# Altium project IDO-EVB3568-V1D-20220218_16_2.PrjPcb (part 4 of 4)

## Sheet P21.SchDoc
size 297 x 209 mm
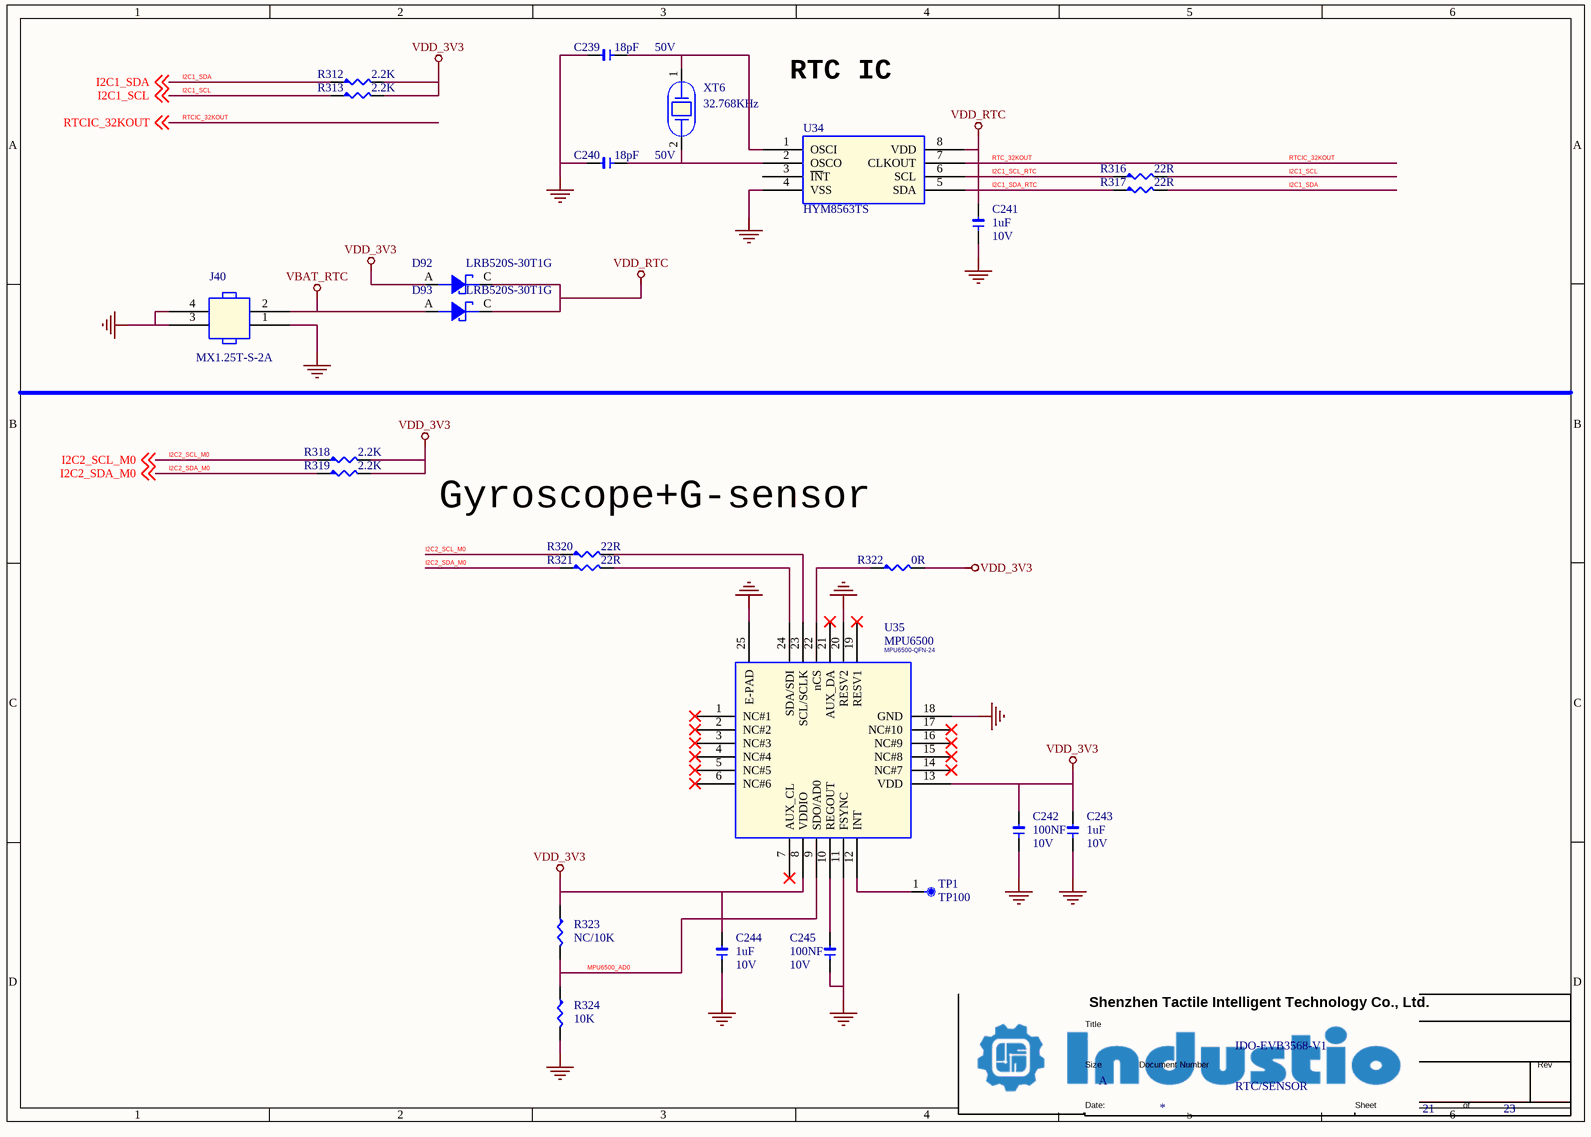
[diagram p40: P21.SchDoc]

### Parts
(Parts that share a designator on the sheet are numbered #1, #2 ... from top to bottom, then left to right.)
*#21  Doc: RTC/SENSOR  Title: IDO-EVB3568-V1  Page Size: A  Page Number: 21  Page Count: 23  (hidden comment: TitleBlock1)  (graphical)
C239  18pF  DSC2: 50V  [1206]
C240  18pF  DSC2: 50V  [1206]
C241  1uF  DSC2: 10V  [1206]
C242  100NF  DSC2: 10V  [1206]
C243  1uF  DSC2: 10V  [1206]
C244  1uF  DSC2: 10V  [1206]
C245  100NF  DSC2: 10V  [1206]
D92  LRB520S-30T1G  [SOD523]
D93  LRB520S-30T1G  [SOD523]
J40  MX1.25T-S-2A  [MX125T-S-2A]
R312  2.2K  [R0402L]
R313  2.2K  [R0402L]
R316  22R  [R0402L]
R317  22R  [R0402L]
R318  2.2K  [R0402L]
R319  2.2K  [R0402L]
R320  22R  [R0402L]
R321  22R  [R0402L]
R322  0R  [R0402L]
R323  NC/10K  [R0402L]
R324  10K  [R0402L]
TP1  TP100  [smd_tp_1mm]
U34  HYM8563TS  [PCF85063ATT-TSSOP8]
U35  MPU6500  [MPU6500-QFN-24]
XT6  32.768KHz  [XTAL_32X15_2P]

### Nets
GND: C239.2 C240.2 C241.1 C242.1 C243.1 C244.1 C245.1 J40.1 J40.3 J40.4 R324.2 U34.4(VSS) U35.11(FSYNC) U35.18(GND) U35.20(RESV2) U35.25(E-PAD)
VBAT_RTC: D93.A J40.2
VDD_3V3: C242.2 C243.2 C244.2 D92.A R312.2 R313.2 R318.2 R319.2 R322.2 R323.1 U35.8(VDDIO) U35.13(VDD)
VDD_RTC: C241.2 D92.C D93.C U34.8(VDD)
I2C1_SCL: R313.1 R316.2 ; off-sheet I2C1_SCL
I2C1_SCL_RTC: R316.1 U34.6(SCL)
I2C1_SDA: R312.1 R317.2 ; off-sheet I2C1_SDA
I2C1_SDA_RTC: R317.1 U34.5(SDA)
I2C2_SCL_M0: R318.1 R320.1 ; off-sheet I2C2_SCL_M0
I2C2_SDA_M0: R319.1 R321.1 ; off-sheet I2C2_SDA_M0
MPU6500_AD0: R323.2 R324.1 U35.9(SDO/AD0)
RTC_32KOUT: U34.7(CLKOUT) ; off-sheet RTCIC_32KOUT  [also labelled RTCIC_32KOUT]
NetC239_1: C239.1 U34.1(OSCI) XT6.1
NetC240_1: C240.1 U34.2(OSCO) XT6.2
NetC245_2: C245.2 U35.10(REGOUT)
NetR320_2: R320.2 U35.23(SCL/SCLK)
NetR321_2: R321.2 U35.24(SDA/SDI)
NetR322_1: R322.1 U35.22(nCS)
NetTP1_1: TP1.1 U35.12(INT)

Not connected (* = marked no-connect by the designer): U34 3(~{IN}T); U35 1(NC#1)* 2(NC#2)* 3(NC#3)* 4(NC#4)* 5(NC#5)* 6(NC#6)* 7(AUX_CL)* 14(NC#7)* 15(NC#8)* 16(NC#9)* 17(NC#10)* 19(RESV1)* 21(AUX_DA)*

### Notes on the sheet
- RTC IC
- Gyroscope+G-sensor

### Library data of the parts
C239 = C-0402_Dup1: Part Number: C020102120027; Part Name: 贴片电容; Manufacture: 三星¦国巨¦村田; ERP Number: 1010200091; DSC1: ±5%; DSC3: C0G; ID: 27; PCB Footprint: C0402L
C240 = C-0402_Dup1: Manufacture: 三星¦国巨¦村田; Part Name: 贴片电容; Part Number: C020102120027; ID: 27; DSC3: C0G; DSC1: ±5%; ERP Number: 1010200091; PCB Footprint: C0402L
C241 = C-0402_Dup1: Part Number: C020102120064; Part Name: 贴片电容; Manufacture: 三星¦国巨¦村田; ERP Number: 1010200054; DSC1: ±10%; DSC3: X5R; ID: 64; PCB Footprint: C0402L
C242 C245 = C-0402_Dup1: Part Number: C020102120060; Part Name: 贴片电容; Manufacture: 三星¦国巨¦村田; DSC1: ±10%; DSC3: X7R; ID: 60; PCB Footprint: C0402L
C243 C244 = C-0402_Dup1: Manufacture: 三星¦国巨¦村田; Part Name: 贴片电容; Part Number: C020102120064; ID: 64; DSC3: X5R; DSC1: ±10%; ERP Number: 1010200054; PCB Footprint: C0402L
D92 D93 = DI-XI-S: Part Number: C040202220002; Part Name: 肖特基二级管; Manufacture: 乐山无线电; CLASS: IC; DSC1: VR=30V; DSC2: IF=200mA; DSC3: VF=350mV/10mA; DSC4: IR=0.5uA; ID: 2; Solder: 推荐
J40 = J-A-2P: Part Number: J020102800058; ID: 6; DSC5: A1251WV-S-2P(CJT); DSC4: 米黄色胶壳 耐高温; DSC3: 立贴; DSC2: 1.25mm间距; DSC1: 2p
R312 R313 R318 R319 = R-0402_Dup1: Part Number: C011002080778; Part Name: 贴片电阻; ID: 778; DSC2: 1/16W; DSC1: ±1%
R316 R317 = R-0402_Dup1: Part Name: 贴片电阻; Part Number: C011002080552; DSC1: ±1%; DSC2: 1/16W; ID: 552
R320 R321 = R-0402_Dup1: Part Number: C011002080552; Part Name: 贴片电阻; ID: 552; DSC2: 1/16W; DSC1: ±1%
R322 = R-0402_Dup1: Part Number: C011002080413; Part Name: 贴片电阻; ID: 413; DSC2: 1/16W; DSC1: ±1%
R323 R324 = R-0402_Dup1: Part Number: C011002080856; Part Name: 贴片电阻; ID: 856; DSC2: 1/16W; DSC1: ±1%; ERP Number: 1010200140
TP1 = TP-TEST: Part Number: CAD; Part Name: 测试点; DSC1: 焊盘1mm; DSC2: 无孔; DSC3: 圆形; DSC4: 单面; ID: 3
U34 = U-PCF85063ATT: Part Name: RTC芯片; Manufacture: NXP; DSC1: RTC,I2C, VCC=0.9-5.5V; DSC2: TSSOP8; DSC3: -40℃~+85℃; ID: 14
U35 = Sensor_MPU6500_1
XT6 = XTAL-2P: Part Name: 贴片无源晶振; Part Number: C050102290002; Manufacture: 泰晶; CLASS: IC; DSC1: 70kΩ; DSC2: ±20ppm; DSC3: 12.5pF; DSC4: -40℃~+85℃; DSC5: 3.2*1.5mm 2P; ID: 2

## Sheet P22.SchDoc
size 420 x 297 mm
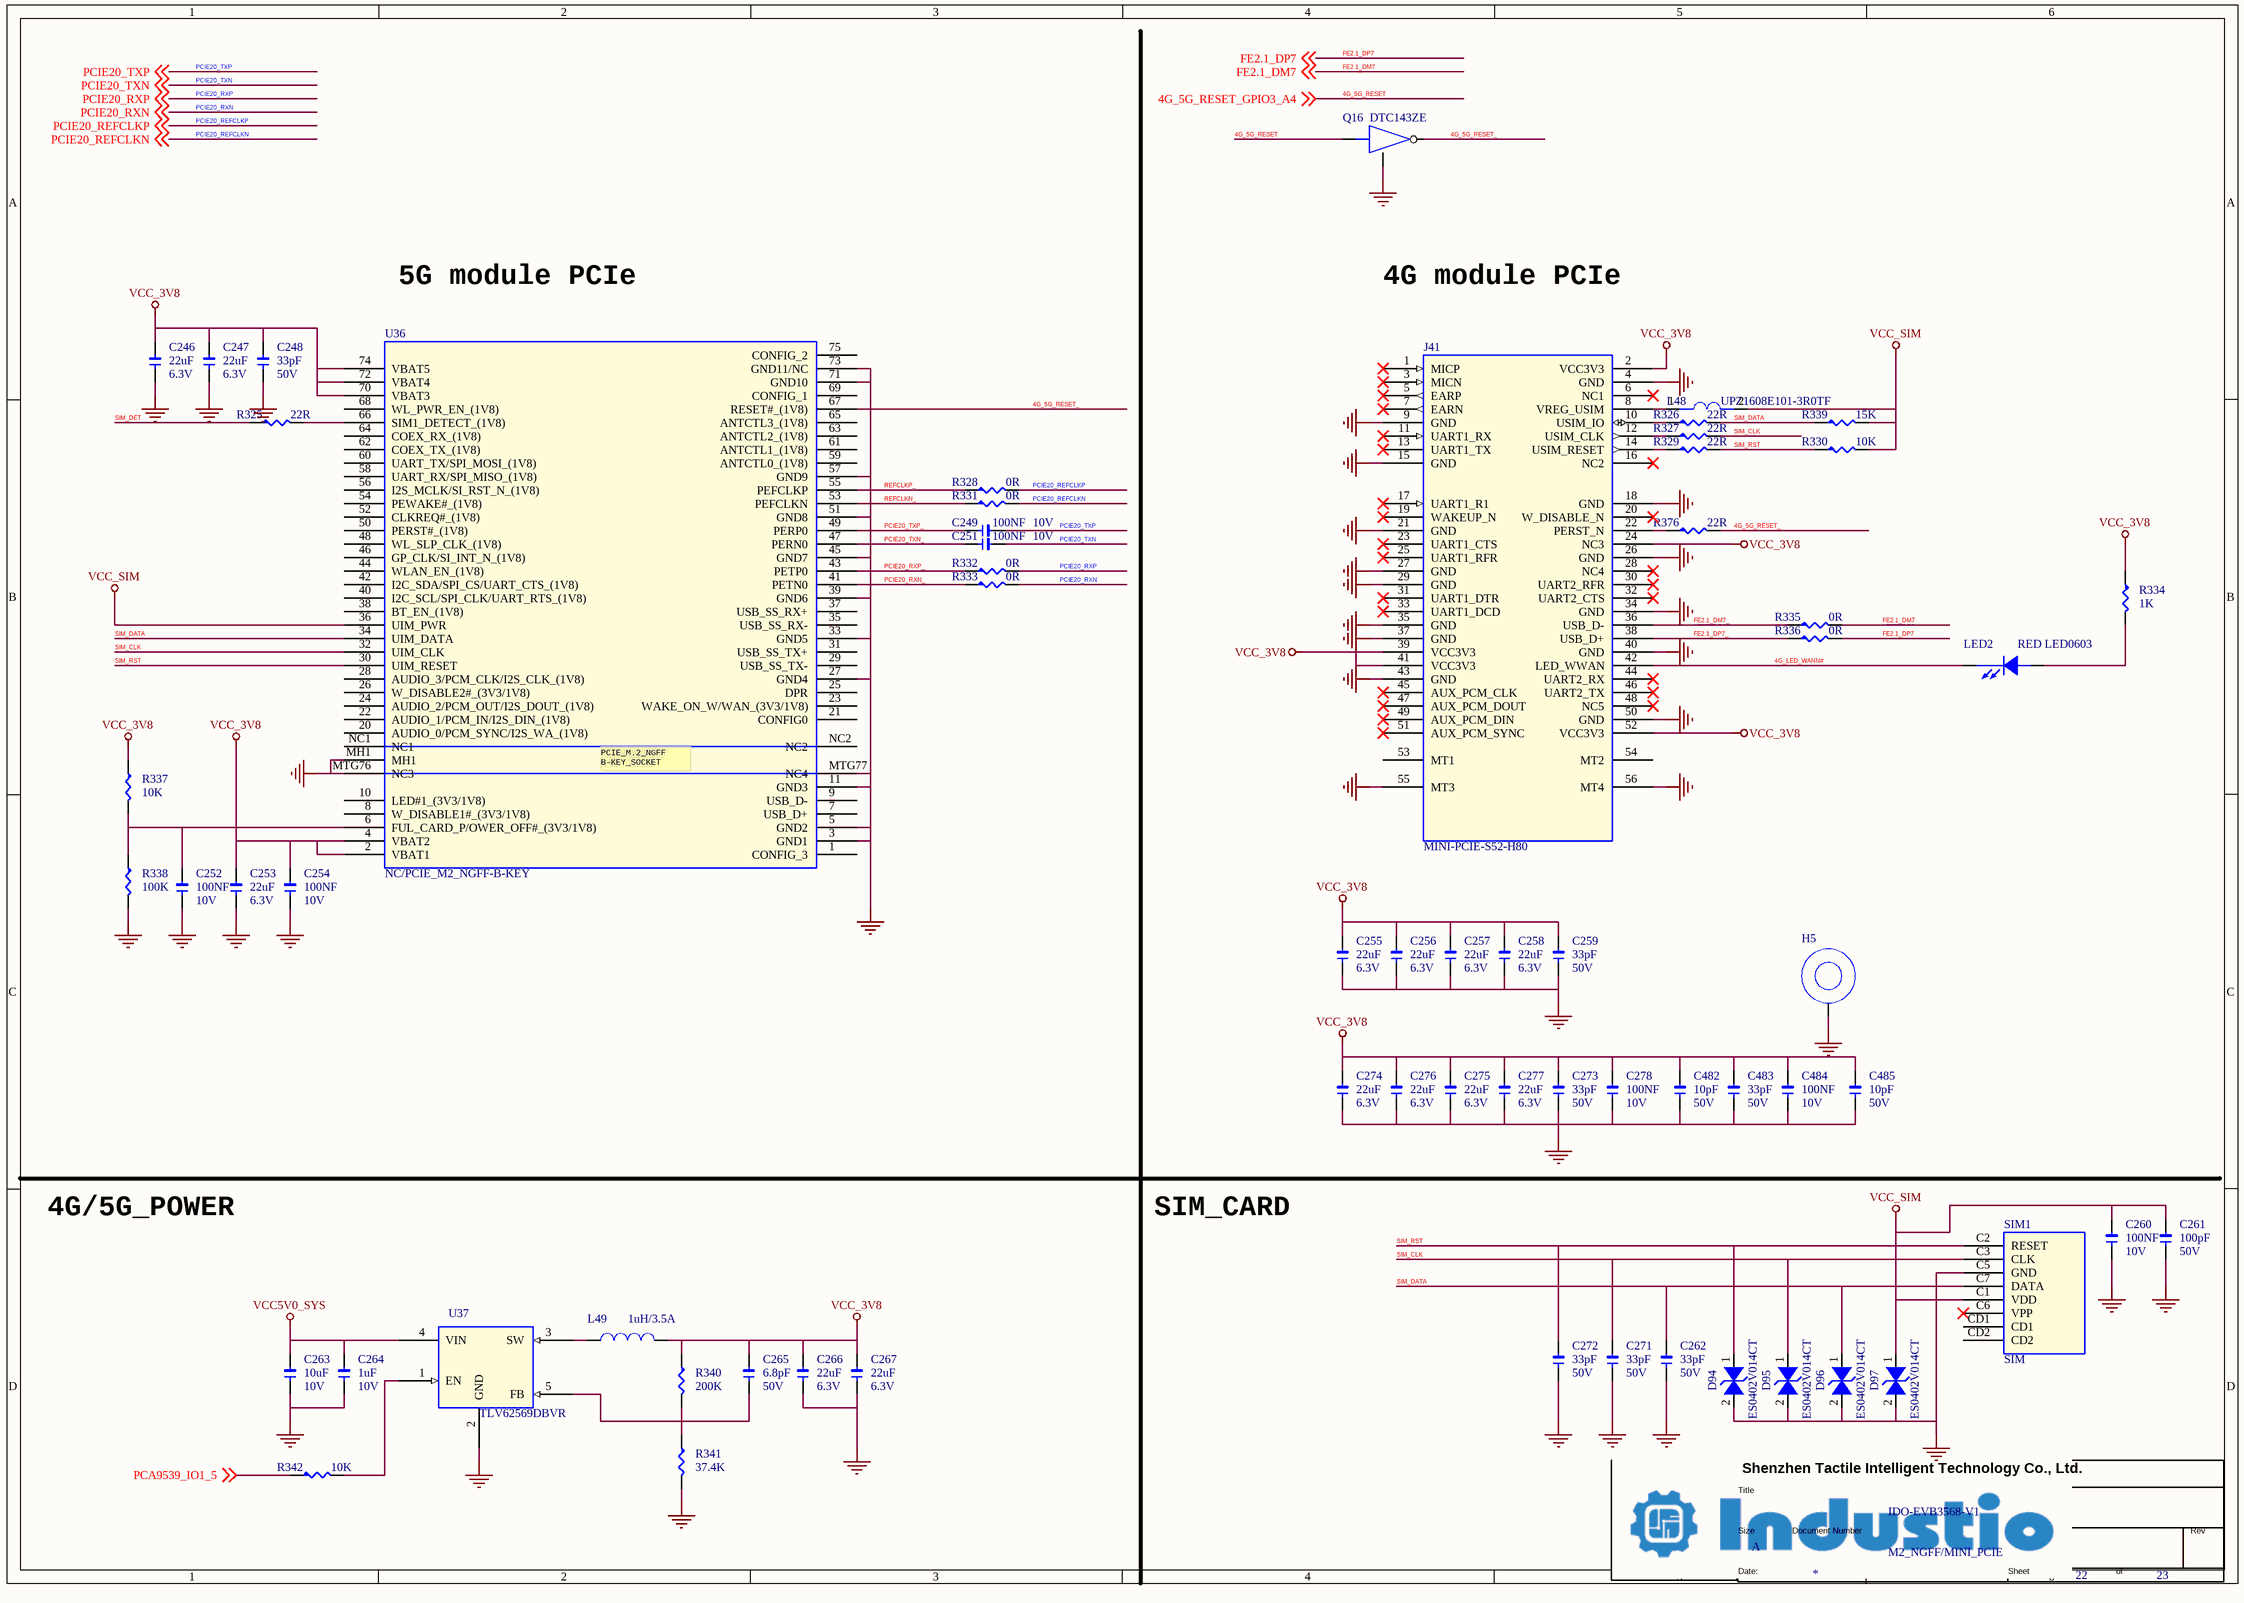
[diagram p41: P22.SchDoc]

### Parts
(Parts that share a designator on the sheet are numbered #1, #2 ... from top to bottom, then left to right.)
*#22  Doc: M2_NGFF/MINI_PCIE  Title: IDO-EVB3568-V1  Page Size: A  Page Number: 22  Page Count: 23  (hidden comment: TitleBlock1)  (graphical)
C246  22uF  DSC2: 6.3V  [1206]
C247  22uF  DSC2: 6.3V  [1206]
C248  33pF  DSC2: 50V  [1206]
C249  100NF  DSC2: 10V  [1206]
C251  100NF  DSC2: 10V  [1206]
C252  100NF  DSC2: 10V  [1206]
C253  22uF  DSC2: 6.3V  [1206]
C254  100NF  DSC2: 10V  [1206]
C255  22uF  DSC2: 6.3V  [1206]
C256  22uF  DSC2: 6.3V  [1206]
C257  22uF  DSC2: 6.3V  [1206]
C258  22uF  DSC2: 6.3V  [1206]
C259  33pF  DSC2: 50V  [1206]
C260  100NF  DSC2: 10V  [1206]
C261  100pF  DSC2: 50V  [1206]
C262  33pF  DSC2: 50V  [1206]
C263  10uF  DSC2: 10V  [1206]
C264  1uF  DSC2: 10V  [1206]
C265  6.8pF  DSC2: 50V  [1206]
C266  22uF  DSC2: 6.3V  [1206]
C267  22uF  DSC2: 6.3V  [1206]
C271  33pF  DSC2: 50V  [1206]
C272  33pF  DSC2: 50V  [1206]
C273  33pF  DSC2: 50V  [1206]
C274  22uF  DSC2: 6.3V  [1206]
C275  22uF  DSC2: 6.3V  [1206]
C276  22uF  DSC2: 6.3V  [1206]
C277  22uF  DSC2: 6.3V  [1206]
C278  100NF  DSC2: 10V  [1206]
C482  10pF  DSC2: 50V  [1206]
C483  33pF  DSC2: 50V  [1206]
C484  100NF  DSC2: 10V  [1206]
C485  10pF  DSC2: 50V  [1206]
D94  ES0402V014CT  [V0402]
D95  ES0402V014CT  [V0402]
D96  ES0402V014CT  [V0402]
D97  ES0402V014CT  [V0402]
H5  Hole  [mtg250_600]  (value not drawn)
J41  MINI-PCIE-S52-H80  [M_MINIPCIE_SOCKET_CK]
L48  UPZ1608E101-3R0TF  [L0603]
L49  1uH/3.5A  [L2520]
LED2  RED LED0603  [LED0603]
Q16  DTC143ZE  [SOT523]
R325  22R  [R0402L]
R326  22R  [R0402L]
R327  22R  [R0402L]
R328  0R  [R0402L]
R329  22R  [R0402L]
R330  10K  [R0402L]
R331  0R  [R0402L]
R332  0R  [R0402L]
R333  0R  [R0402L]
R334  1K  [R0402L]
R335  0R  [R0402L]
R336  0R  [R0402L]
R337  10K  [R0402L]
R338  100K  [R0402L]
R339  15K  [R0402L]
R340  200K  [R0402L]
R341  37.4K  [R0402L]
R342  10K  [R0402L]
R376  22R  [R0402L]
SIM1  SIM  [SIM-91288-021]
U36  NC/PCIE_M2_NGFF-B-KEY  [PCIE_M2_NGFF-B-KEY]
U37  TLV62569DBVR  [SOT23-5]

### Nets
GND: C246.1 C247.1 C248.1 C252.1 C253.1 C254.1 C255.1 C256.1 C257.1 C258.1 C259.1 C260.1 C261.1 C262.1 C263.1 C264.1 C266.1 C267.1 C271.1 C272.1 C273.1 C274.1 C275.1 C276.1 C277.1 C278.1 C482.1 C483.1 C484.1 C485.1 D94.2(I/O1) D95.2(I/O1) D96.2(I/O1) D97.2(I/O1) H5.1 J41.4(GND) J41.9(GND) J41.15(GND) J41.18(GND) J41.21(GND) J41.26(GND) J41.27(GND) J41.29(GND) J41.34(GND) J41.35(GND) J41.37(GND) J41.40(GND) J41.43(GND) J41.50(GND) J41.55(MT3) J41.56(MT4) Q16.2 R338.2 R341.2 SIM1.C5(GND) U36.3(GND1) U36.5(GND2) U36.11(GND3) U36.27(GND4) U36.33(GND5) U36.39(GND6) U36.45(GND7) U36.51(GND8) U36.57(GND9) U36.71(GND10) U36.73(GND11/NC) U36.MH1 U36.MTG76(NC3) U36.MTG77(NC4) U37.2(GND)
VCC5V0_SYS: C263.2 C264.2 U37.4(VIN)
VCC_3V8: C246.2 C247.2 C248.2 C253.2 C254.2 C255.2 C256.2 C257.2 C258.2 C259.2 C265.2 C266.2 C267.2 C273.2 C274.2 C275.2 C276.2 C277.2 C278.2 C482.2 C483.2 C484.2 C485.2 J41.2(VCC3V3) J41.24(NC3) J41.39(VCC3V3) J41.41(VCC3V3) J41.52(VCC3V3) L49.2 R334.1 R337.1 R340.1 U36.2(VBAT1) U36.4(VBAT2) U36.70(VBAT3) U36.72(VBAT4) U36.74(VBAT5)
VCC_SIM: C260.2 C261.2 D97.1(I/O2) L48.2 R330.2 R339.2 SIM1.C1(VDD) U36.36(UIM_PWR)
4G_5G_RESET: Q16.1 ; off-sheet 4G_5G_RESET_GPIO3_A4  [also labelled 4G_5G_RESET_GPIO3_A4]
4G_5G_RESET_: Q16.3 R376.2 U36.67(RESET#_(1V8))
4G_LED_WANN#: J41.42(LED_WWAN) LED2.C(CATHODE)
FE2.1_DM7: R335.2 ; off-sheet FE2.1_DM7
FE2.1_DM7_: J41.36(USB_D-) R335.1
FE2.1_DP7: R336.2 ; off-sheet FE2.1_DP7
FE2.1_DP7_: J41.38(USB_D+) R336.1
PCA9539_IO1_5: R342.1 ; off-sheet PCA9539_IO1_5
PCIE20_REFCLKN: R331.2 ; off-sheet PCIE20_REFCLKN
PCIE20_REFCLKP: R328.2 ; off-sheet PCIE20_REFCLKP
PCIE20_RXN: R333.2 ; off-sheet PCIE20_RXN
PCIE20_RXN_: R333.1 U36.41(PETN0)
PCIE20_RXP: R332.2 ; off-sheet PCIE20_RXP
PCIE20_RXP_: R332.1 U36.43(PETP0)
PCIE20_TXN: C251.2 ; off-sheet PCIE20_TXN
PCIE20_TXN_: C251.1 U36.47(PERN0)
PCIE20_TXP: C249.2 ; off-sheet PCIE20_TXP
PCIE20_TXP_: C249.1 U36.49(PERP0)
REFCLKN_: R331.1 U36.53(PEFCLKN)
REFCLKP_: R328.1 U36.55(PEFCLKP)
SIM_CLK: C271.2 D95.1(I/O2) R327.2 SIM1.C3(CLK) U36.32(UIM_CLK)
SIM_DATA: C262.2 D96.1(I/O2) R326.2 R339.1 SIM1.C7(DATA) U36.34(UIM_DATA)
SIM_DET: R325.1
SIM_RST: C272.2 D94.1(I/O2) R329.2 R330.1 SIM1.C2(RESET) U36.30(UIM_RESET)
NetC252_2: C252.2 R337.2 R338.1 U36.6(FUL_CARD_P/OWER_OFF#_(3V3/1V8))
NetC265_1: C265.1 R340.2 R341.1 U37.5(FB)
NetJ41_8: J41.8(VREG_USIM) L48.1
NetJ41_10: J41.10(USIM_IO) R326.1
NetJ41_12: J41.12(USIM_CLK) R327.1
NetJ41_14: J41.14(USIM_RESET) R329.1
NetJ41_22: J41.22(PERST_N) R376.1
NetL49_1: L49.1 U37.3(SW)
NetLED2_A: LED2.A(ANODE) R334.2
NetR325_2: R325.2 U36.66(SIM1_DETECT_(1V8))
NetR342_2: R342.2 U37.1(EN)

Not connected (* = marked no-connect by the designer): J41 1(MICP)* 3(MICN)* 5(EARP)* 6(NC1)* 7(EARN)* 11(UART1_RX)* 13(UART1_TX)* 16(NC2)* 17(UART1_R1)* 19(WAKEUP_N)* 20(W_DISABLE_N)* 23(UART1_CTS)* 25(UART1_RFR)* 28(NC4)* 30(UART2_RFR)* 31(UART1_DTR)* 32(UART2_CTS)* 33(UART1_DCD)* 44(UART2_RX)* 45(AUX_PCM_CLK)* 46(UART2_TX)* 47(AUX_PCM_DOUT)* 48(NC5)* 49(AUX_PCM_DIN)* 51(AUX_PCM_SYNC)* 53(MT1) 54(MT2); SIM1 C6(VPP)* CD1 CD2; U36 1(CONFIG_3) 7(USB_D+) 8(W_DISABLE1#_(3V3/1V8)) 9(USB_D-) 10(LED#1_(3V3/1V8)) 20(AUDIO_0/PCM_SYNC/I2S_WA_(1V8)) 21(CONFIG0) 22(AUDIO_1/PCM_IN/I2S_DIN_(1V8)) 23(WAKE_ON_W/WAN_(3V3/1V8)) 24(AUDIO_2/PCM_OUT/I2S_DOUT_(1V8)) 25(DPR) 26(W_DISABLE2#_(3V3/1V8)) 28(AUDIO_3/PCM_CLK/I2S_CLK_(1V8)) 29(USB_SS_TX-) 31(USB_SS_TX+) 35(USB_SS_RX-) 37(USB_SS_RX+) 38(BT_EN_(1V8)) 40(I2C_SCL/SPI_CLK/UART_RTS_(1V8)) 42(I2C_SDA/SPI_CS/UART_CTS_(1V8)) 44(WLAN_EN_(1V8)) 46(GP_CLK/SI_INT_N_(1V8)) 48(WL_SLP_CLK_(1V8)) 50(PERST#_(1V8)) 52(CLKREQ#_(1V8)) 54(PEWAKE#_(1V8)) 56(I2S_MCLK/SI_RST_N_(1V8)) 58(UART_RX/SPI_MISO_(1V8)) 59(ANTCTL0_(1V8)) 60(UART_TX/SPI_MOSI_(1V8)) 61(ANTCTL1_(1V8)) 62(COEX_TX_(1V8)) 63(ANTCTL2_(1V8)) 64(COEX_RX_(1V8)) 65(ANTCTL3_(1V8)) 68(WL_PWR_EN_(1V8)) 69(CONFIG_1) 75(CONFIG_2) NC1 NC2

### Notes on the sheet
- 5G module PCIe
- 4G module PCIe
- 4G/5G_POWER
- SIM_CARD

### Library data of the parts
C246 C247 C255-C258 C267 C274-C277 = C-0603: Part Number: C020102120072; Part Name: 贴片电容; Manufacture: 三星¦国巨¦村田; PCB Footprint: C0603L; ERP Number: 1010200133; DSC1: ±20%; DSC3: X5R; ID: 72
C248 C259 C273 C483 = C-0402_Dup1: Part Number: C020102120033; Part Name: 贴片电容; Manufacture: 三星¦国巨¦村田; PCB Footprint: C0402L; ERP Number: 1010200087; DSC1: ±5%; DSC3: C0G; ID: 33
C249 C251 C278 C484 = C-0402_Dup1: Part Number: C020102120060; Part Name: 贴片电容; Manufacture: 三星¦国巨¦村田; PCB Footprint: C0402L; DSC1: ±10%; DSC3: X7R; ID: 60
C252 C254 = C-0402_Dup1: Manufacture: 三星¦国巨¦村田; Part Name: 贴片电容; Part Number: C020102120060; PCB Footprint: C0402L; ID: 60; DSC3: X7R; DSC1: ±10%
C253 C266 = C-0603: Manufacture: 三星¦国巨¦村田; Part Name: 贴片电容; Part Number: C020102120072; PCB Footprint: C0603L; ID: 72; DSC3: X5R; DSC1: ±20%; ERP Number: 1010200133
C260 = C-0402_Dup1: as C242 on sheet P21
C261 = C-0402_Dup1: Part Number: C020102120040; Part Name: 贴片电容; Manufacture: 三星¦国巨¦村田; ERP Number: 1010200152; DSC1: ±5%; DSC3: C0G; ID: 40; PCB Footprint: C0402L
C262 C271 C272 = C-0402_Dup1: Manufacture: 三星¦国巨¦村田; Part Name: 贴片电容; Part Number: C020102120033; ID: 33; DSC3: C0G; DSC1: ±5%; ERP Number: 1010200087; PCB Footprint: C0402L
C263 = C-0603: Manufacture: 三星¦国巨¦村田; Part Name: 贴片电容; Part Number: C020102120071; PCB Footprint: C0603L; ID: 71; DSC3: X5R; DSC1: ±20%; ERP Number: 1010200076
C264 = C-0402_Dup1: Manufacture: 三星¦国巨¦村田; Part Name: 贴片电容; Part Number: C020102120064; PCB Footprint: C0402L; ID: 64; DSC3: X5R; DSC1: ±10%; ERP Number: 1010200054
C265 = C-0402_Dup1: Part Number: C020102120018; Part Name: 贴片电容; Manufacture: 三星¦国巨¦村田; PCB Footprint: C0402L; ERP Number: 1010200056; DSC1: ±0.25PF; DSC3: C0G; ID: 18
C482 C485 = C-0402_Dup1: Part Number: C020102120021; Part Name: 贴片电容; Manufacture: 三星¦国巨¦村田; PCB Footprint: C0402L; ERP Number: 1010200151; DSC1: ±5%; DSC3: C0G; ID: 21
D94 D95 D97 = DI-ESD: ESD 0402; Part Number: C040502250002; Manufacture P/N: MLVG04021R0UV18; Manufacturer: INPAQ; Manufacture: AEM; PN Type: Varistor; ID: 2; DSC5: Cj=0.25pF; DSC4: Vc=30V; DSC3: Vbr=300V; DSC2: Vdc=14V; DSC1: 双向; ERP Number: 1010800023
D96 = DI-ESD: ESD 0402; Part Number: C040502250002; Manufacture P/N: MLVG04021R0UV18; Manufacturer: INPAQ; Manufacture: AEM; PN Type: Varistor; ERP Number: 1010800023; DSC1: 双向; DSC2: Vdc=14V; DSC3: Vbr=300V; DSC4: Vc=30V; DSC5: Cj=0.25pF; ID: 2
J41 = J-MINIPCIE-52P_0: Part Name: 金手指连接器; Part Number: J050102900003; CLASS: IO; ID: 3; DSC4: 91304-80-052R2(UMaxconn); DSC3: 贴片; DSC2: 52P; DSC1: miniPCIE座子 H=8.0mm
L48 = FB-0603: SMD Multilayer Ferrite Chip Bead,3A,30Ohm,0.03R; Part Number: C060502370005; Manufacture P/N: PZ1608D300-3R0TF; Manufacture2 P/N: PBY160808T-400Y-N; Manufacturer: SUNLORD; Part Name: 贴片磁珠; Manufacture: 顺络; PN Type: SMD FERRITE BEAD; ERP Number: 1010200207; DSC1: 100Ω@100MHz; DSC3: DCR=30mΩ; DSC4: 电源线; ID: 5
L49 = L-IND_Dup1: Manufacture: 顺络; Part Number: C060202340012; Part Name: 功率电感; ID: 12; DSC6: WPN252012E1R0MT(顺络); DSC5: 2.5*2.0*1.2mm; DSC4: 37mΩ; DSC3: Irms=3.5A; DSC2: Isat=4.5A; DSC1: ±20%
LED2 = D-LED0603: Part Name: LED; Part Number: C140202660001; ID: 5; DSC3: 19-217/R6C-AL1M2VY/3T(亿光); DSC2: NCD0603R1(国星光电); DSC1: 红色LED，SMD,0603，VF=2V; ERP Number: 1010800005
Q16 = S-NPN_Dup1: Manufacture: 长电; Part Name: 数字三极管; Part Number: C030302200002; ID: 2; DSC4: 150mW; DSC3: Vce=50V; DSC2: Ic=100mA; DSC1: NPN; ERP Number: 1010800049
R325 R376 = R-0402_Dup1: as R320 on sheet P21
R326 R327 R329 = R-0402_Dup1: as R316 on sheet P21
R328 = R-0402_Dup1: as R322 on sheet P21
R330 R337 R342 = R-0402_Dup1: Part Name: 贴片电阻; Part Number: C011002080856; ERP Number: 1010200140; DSC1: ±1%; DSC2: 1/16W; ID: 856
R331-R333 R335 R336 = R-0402_Dup1: Part Name: 贴片电阻; Part Number: C011002080413; DSC1: ±1%; DSC2: 1/16W; ID: 413
R334 = R-0402_Dup1: Part Number: C011002080742; Part Name: 贴片电阻; ID: 742; DSC2: 1/16W; DSC1: ±1%; ERP Number: 1010200113
R338 = R-0402_Dup1: Part Number: C011002080976; Part Name: 贴片电阻; ID: 976; DSC2: 1/16W; DSC1: ±1%; ERP Number: 1010200137
R339 = R-0402_Dup1: Part Number: C011002080875; Part Name: 贴片电阻; ID: 875; DSC2: 1/16W; DSC1: ±1%; ERP Number: 1010200458
R340 = R-0402_Dup1: Part Number: C011002081009; Part Name: 贴片电阻; ID: 1,009; DSC2: 1/16W; DSC1: ±1%; ERP Number: 1010200139
R341 = R-0402_Dup1: Part Number: C011002080922; Part Name: 贴片电阻; ID: 922; DSC2: 1/16W; DSC1: ±1%; ERP Number: 1010200444
SIM1 = J-SIM-021_0: Part Number: J080202990002; Part Name: SIM卡座; ERP Number: 1040100109; DSC1: SIM卡座 91228 抽屉式 8P; DSC2: 31.0*25.1*26mm; DSC3: 贴片; DSC4: SIM-021(硕方); ID: 5
U36 = PCIE_M2_NGFF-B-KEY_2
U37 = U-TLV62569DBVR: Part Name: DCDC; Part Number: C070202410003; Manufacture: TI; DSC1: Vi=2.5-5.5V; DSC2: Vo=0.6-5.5V; DSC3: Io=2A; DSC4: Vfb=0.6V; DSC5: 0.95; DSC6: 1.5MHz; DSC7: 同步降压 轻载效率 低Iq; Solder: 推荐; ID: 3

## Sheet P23.SchDoc
size 297 x 209 mm
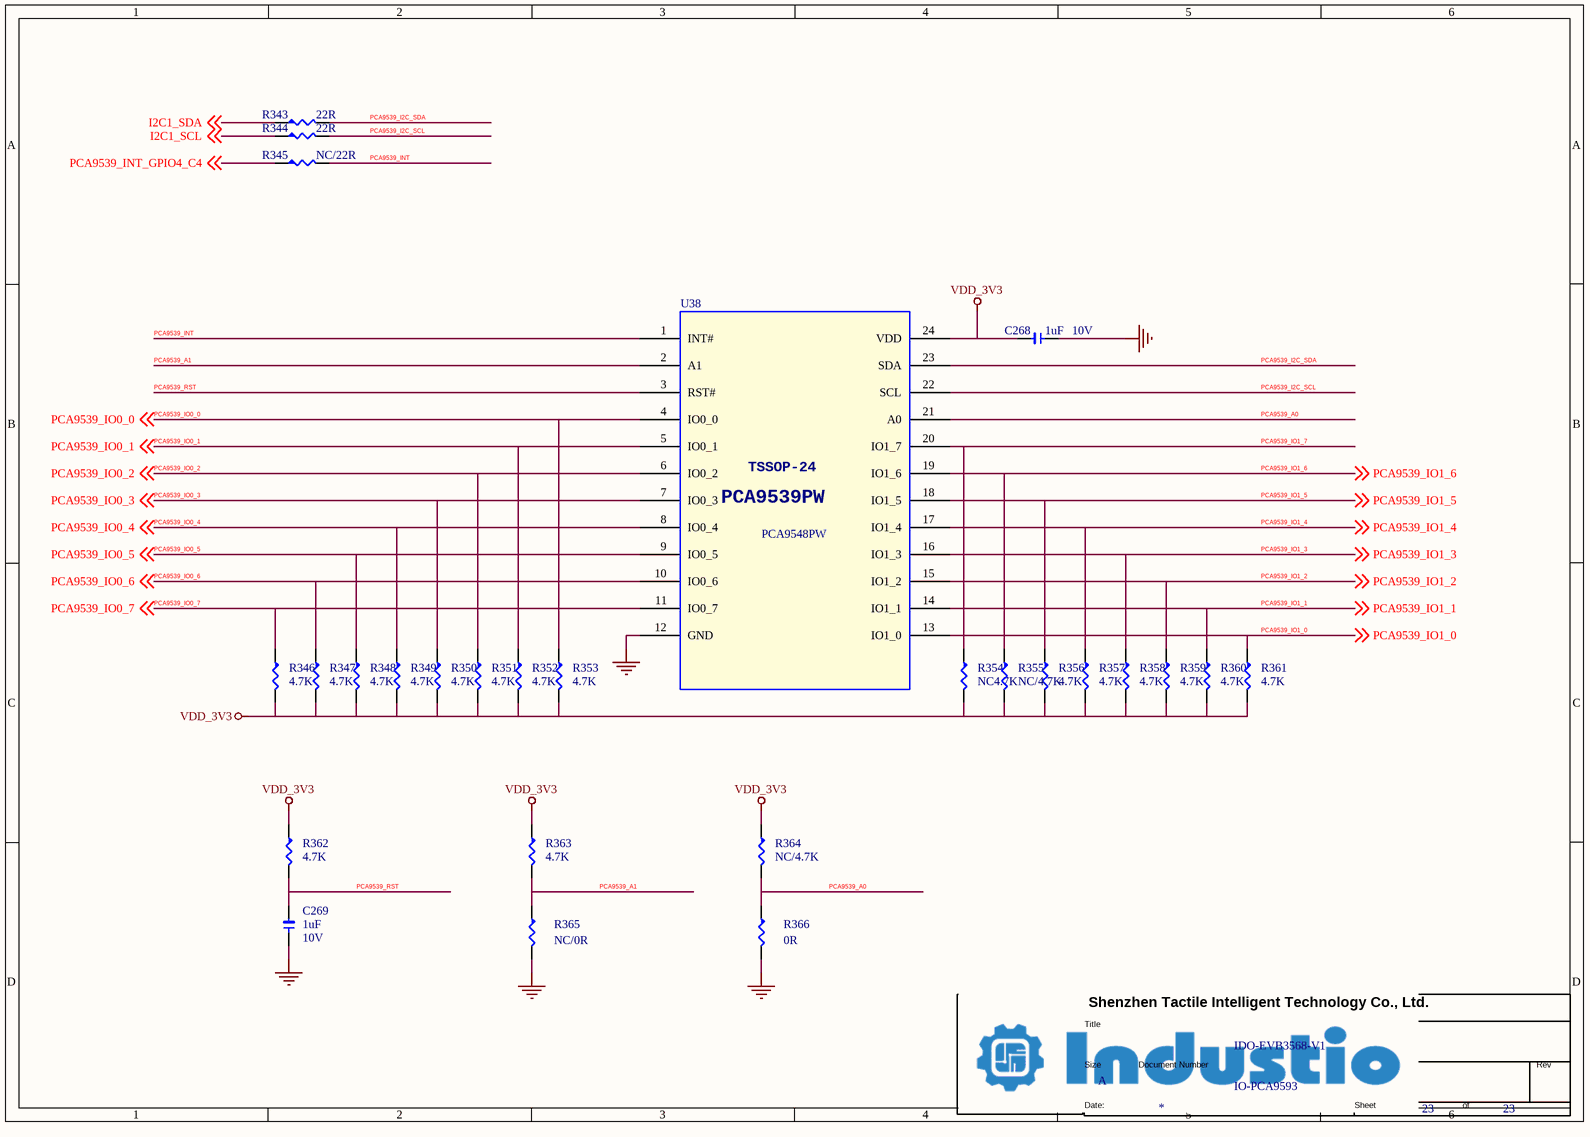
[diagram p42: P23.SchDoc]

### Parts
(Parts that share a designator on the sheet are numbered #1, #2 ... from top to bottom, then left to right.)
*#23  Doc: IO-PCA9593  Title: IDO-EVB3568-V1  Page Size: A  Page Number: 23  (hidden comment: TitleBlock1)  (graphical)
C268  1uF  DSC2: 10V  [1206]
C269  1uF  DSC2: 10V  [1206]
R343  22R  [R0402L]
R344  22R  [R0402L]
R345  NC/22R  [R0402L]
R346  4.7K  [R0402L]
R347  4.7K  [R0402L]
R348  4.7K  [R0402L]
R349  4.7K  [R0402L]
R350  4.7K  [R0402L]
R351  4.7K  [R0402L]
R352  4.7K  [R0402L]
R353  4.7K  [R0402L]
R354  NC4.7K  [R0402L]
R355  NC/4.7K  [R0402L]
R356  4.7K  [R0402L]
R357  4.7K  [R0402L]
R358  4.7K  [R0402L]
R359  4.7K  [R0402L]
R360  4.7K  [R0402L]
R361  4.7K  [R0402L]
R362  4.7K  [R0402L]
R363  4.7K  [R0402L]
R364  NC/4.7K  [R0402L]
R365  NC/0R  [R0402L]
R366  0R  [R0402L]
U38  PCA9548PW  [PCA9539PW-TSSOP24]

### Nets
GND: C268.1 C269.1 R365.2 R366.2 U38.12(GND)
VDD_3V3: C268.2 R346.2 R347.2 R348.2 R349.2 R350.2 R351.2 R352.2 R353.2 R354.2 R355.2 R356.2 R357.2 R358.2 R359.2 R360.2 R361.2 R362.1 R363.1 R364.1 U38.24(VDD)
I2C1_SCL: R344.1 ; off-sheet I2C1_SCL
I2C1_SDA: R343.1 ; off-sheet I2C1_SDA
PCA9539_A0: R364.2 R366.1 U38.21(A0)
PCA9539_A1: R363.2 R365.1 U38.2(A1)
PCA9539_I2C_SCL: R344.2 U38.22(SCL)
PCA9539_I2C_SDA: R343.2 U38.23(SDA)
PCA9539_INT: R345.2 U38.1(INT#)
PCA9539_INT_GPIO4_C4: R345.1 ; off-sheet PCA9539_INT_GPIO4_C4  [project net EDP_HPDIN_M0/SPDIF_TX_M2/SATA2_ACT_LED/PCIE30X2_PERSTn_M2/I2S3_LRCK_M1/GPIO4_C4_d]
PCA9539_IO0_0: R353.1 U38.4(IO0_0) ; off-sheet PCA9539_IO0_0
PCA9539_IO0_1: R352.1 U38.5(IO0_1) ; off-sheet PCA9539_IO0_1
PCA9539_IO0_2: R351.1 U38.6(IO0_2) ; off-sheet PCA9539_IO0_2
PCA9539_IO0_3: R350.1 U38.7(IO0_3) ; off-sheet PCA9539_IO0_3
PCA9539_IO0_4: R349.1 U38.8(IO0_4) ; off-sheet PCA9539_IO0_4
PCA9539_IO0_5: R348.1 U38.9(IO0_5) ; off-sheet PCA9539_IO0_5
PCA9539_IO0_6: R347.1 U38.10(IO0_6) ; off-sheet PCA9539_IO0_6
PCA9539_IO0_7: R346.1 U38.11(IO0_7) ; off-sheet PCA9539_IO0_7
PCA9539_IO1_0: R361.1 U38.13(IO1_0) ; off-sheet PCA9539_IO1_0
PCA9539_IO1_1: R360.1 U38.14(IO1_1) ; off-sheet PCA9539_IO1_1
PCA9539_IO1_2: R359.1 U38.15(IO1_2) ; off-sheet PCA9539_IO1_2  [project net LCM_VIO_EN]
PCA9539_IO1_3: R358.1 U38.16(IO1_3) ; off-sheet PCA9539_IO1_3  [project net LVDS_ON]
PCA9539_IO1_4: R357.1 U38.17(IO1_4) ; off-sheet PCA9539_IO1_4
PCA9539_IO1_5: R356.1 U38.18(IO1_5) ; off-sheet PCA9539_IO1_5
PCA9539_IO1_6: R355.1 U38.19(IO1_6) ; off-sheet PCA9539_IO1_6  [project net EDP_ON]
PCA9539_IO1_7: R354.1 U38.20(IO1_7)
PCA9539_RST: C269.2 R362.2 U38.3(RST#)

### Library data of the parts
C268 C269 = C-0402_Dup1: as C243 on sheet P21
R343 R344 = R-0402_Dup1: as R320 on sheet P21
R345 = R-0402_Dup1: as R316 on sheet P21
R346-R355 R363 R364 = R-0402_Dup1: Part Name: 贴片电阻; Part Number: C011002080818; ERP Number: 1010200445; DSC1: ±1%; DSC2: 1/16W; ID: 818
R356-R362 = R-0402_Dup1: Part Number: C011002080818; Part Name: 贴片电阻; ID: 818; DSC2: 1/16W; DSC1: ±1%; ERP Number: 1010200445
R365 R366 = R-0402_Dup1: as R331-R333 on sheet P22
U38 = 5962-87786_1

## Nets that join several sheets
GND: P04 (31 pins), P05 (14 pins), P06 (20 pins), P07 (34 pins), P08 (89 pins), P09 (16 pins), P10 (34 pins), P11 (19 pins), P12 (13 pins), P13 (27 pins), P14 (35 pins), P15 (41 pins), P16 (24 pins), P17 (25 pins), P18 (42 pins), P19 (44 pins), P20 (65 pins), P21 (16 pins), P22 (70 pins), P23 (5 pins)
GND_EARTH: P04 (H1.1 H2.1 H3.1 H4.1), P18 (J30.SH1 J30.SH2), P19 (C206.2 J31.SH1 J31.SH2 R265.2)
VCC3V3_SD: P05 (M5.69), P06 (C35.2 D2.1 J3.4)
VCC5V0_SYS: P04 (11 pins), P05 (7 pins), P08 (L13.1 R44.2), P10 (L21.1), P12 (5 pins), P13 (C113.2 C114.2 L27.1 U15.6), P14 (C121.2 C122.2 L28.1 U16.6), P15 (5 pins), P20 (13 pins), P22 (C263.2 C264.2 U37.4)
VCC12V_DCIN: P04 (11 pins), P12 (J20.1 J21.5 J21.6), P15 (J25.1 J27.5 J27.6)
VCC_1V8: P05 (M5.103), P09 (R60.1 R61.1), P15 (C132.2 L30.2), P16 (R146.2 R147.2), P17 (R172.1), P18 (R221.1), P19 (R269.1)
VCC_3V3: P04 (R14.1), P05 (M5.104)
VCCIO_PHY1: P18 (5 pins), P19 (12 pins)
VCCIO_WL: P17 (11 pins), P20 (Q15.1 R305.1 R308.1)
VDD_3V3: P04 (6 pins), P06 (R25.1), P08 (L11.1), P10 (L16.1 L22.1 R72.1), P11 (5 pins), P12 (5 pins), P13 (C117.2 J22.38 J22.39 R103.1), P14 (8 pins), P15 (C128.2 J25.5 L29.2 R126.1), P16 (9 pins), P17 (7 pins), P18 (R222.1 R229.1), P19 (R270.1 R277.1), P20 (12 pins), P21 (12 pins), P23 (21 pins)
VDD_USB_5V: P04 (6 pins), P07 (6 pins), P08 (15 pins), P09 (J14.1), P11 (D49.A D51.A Q5.1)
4G_5G_RESET: P05 (M5.123), P22 (Q16.1)
BT_REG_ON_H_GPIO3_A7: P05 (M5.120), P17 (R160.1)
BT_WAKE_HOST_H_GPIO3_A1: P05 (M5.126), P17 (Q11.3 R165.2 R170.1)
CAM_CLKOUT0/EBC_SDCE1/GMAC1_RXD0_M1/SPI3_CS1_M0/I2S1_LRCK_RX_M1/GPIO4_A7_d: P05 (M5.80), P19 (R271.2)
CAM_CLKOUT1/EBC_SDCE2/GMAC1_RXD1_M1/SPI3_MISO_M0/I2S1_SDO1_M1/GPIO4_B0_d: P05 (M5.79), P19 (R272.2)
CAN1_RX_M0: P05 (M5.36), P20 (D90.A R302.1)
CAN1_TX_M0: P05 (M5.37), P20 (U32.1)
CAN2_RX_M0: P05 (M5.75), P20 (D107.A R305.2)
CAN2_TX_M0: P05 (M5.74), P20 (Q15.2 R308.2)
CIF_CLKIN/EBC_SDCLK/GMAC1_MCLKINOUT_M1/UART1_CTSn_M1/I2S2_SCLK_RX_M1/GPIO4_C1_d: P05 (M5.70), P19 (C194.2 R240.1 R241.1)
CIF_CLKOUT/EBC_GDCLK/PWM11_IR_M1/GPIO4_C0_d: P05 (M5.71), P16 (R143.1)
CIF_D0/EBC_SDDO0/SDMMC2_D0_M0/I2S1_MCLK_M1/VOP_BT656_D0_M1/GPIO3_C6_d: P05 (M5.97), P17 (R152.2 R153.1)
CIF_D1/EBC_SDDO1/SDMMC2_D1_M0/I2S1_SCLK_TX_M1/VOP_BT656_D1_M1/GPIO3_C7_d: P05 (M5.96), P17 (R154.1)
CIF_D2/EBC_SDDO2/SDMMC2_D2_M0/I2S1_LRCK_TX_M1/VOP_BT656_D2_M1/GPIO3_D0_d: P05 (M5.95), P17 (R155.1)
CIF_D3/EBC_SDDO3/SDMMC2_D3_M0/I2S1_SDO0_M1/VOP_BT656_D3_M1/GPIO3_D1_d: P05 (M5.94), P17 (R156.1)
CIF_D4/EBC_SDDO4/SDMMC2_CMD_M0/I2S1_SDI0_M1/VOP_BT656_D4_M1/GPIO3_D2_d: P05 (M5.93), P17 (R157.2 R158.1)
CIF_D5/EBC_SDDO5/SDMMC2_CLK_M0/I2S1_SDI1_M1/VOP_BT656_D5_M1/GPIO3_D3_d: P05 (M5.92), P17 (R159.1)
CIF_D6/EBC_SDDO6/SDMMC2_DET_M0/I2S1_SDI2_M1/VOP_BT656_D6_M1/GPIO3_D4_d: P05 (M5.91), P17 (R168.1 R182.1)
CIF_D7/EBC_SDDO7/SDMMC2_PWREN_M0/I2S1_SDI3_M1/VOP_BT656_D7_M1/GPIO3_D5_d: P05 (M5.90), P17 (U23.13)
CIF_D8/EBC_SDDO8/GMAC1_TXD2_M1/UART1_TX_M1/PDM_CLK0_M1/GPIO3_D6_d: P05 (M5.89), P19 (R248.1)
CIF_D9/EBC_SDDO9/GMAC1_TXD3_M1/UART1_RX_M1/PDM_SDI0_M1/GPIO3_D7_d: P05 (M5.88), P19 (R249.1)
CIF_D10/EBC_SDDO10/GMAC1_TXCLK_M1/PDM_CLK1_M1/GPIO4_A0_d: P05 (M5.87), P19 (C494.2 R253.1)
CIF_D11/EBC_SDDO11/GMAC1_RXD2_M1/PDM_SDI1_M1/GPIO4_A1_d: P05 (M5.86), P19 (R273.2)
CIF_D12/EBC_SDDO12/GMAC1_RXD3_M1/UART7_TX_M2/PDM_SDI2_M1/GPIO4_A2_d: P05 (M5.85), P19 (R274.2)
CIF_D13/EBC_SDDO13/GMAC1_RXCLK_M1/UART7_RX_M2/PDM_SDI3_M1/GPIO4_A3_d: P05 (M5.84), P19 (C211.2 R275.2)
CIF_D14/EBC_SDDO14/GMAC1_TXD0_M1/UART9_TX_M2/I2S2_LRCK_TX_M1/GPIO4_A4_d: P05 (M5.83), P19 (R244.1)
CIF_D15/EBC_SDDO15/GMAC1_TXD1_M1/UART9_RX_M2/I2S2_LRCK_RX_M1/GPIO4_A5_d: P05 (M5.82), P19 (R245.1)
CIF_HREF/EBC_SDLE/GMAC1_MDC_M1/UART1_RTSn_M1/I2S2_MCLK_M1/GPIO4_B6_d: P05 (M5.73), P19 (U25.13)
CIF_VSYNC/EBC_SDOE/GMAC1_MDIO_M1/I2S2_SCLK_TX_M1/GPIO4_B7_d: P05 (M5.72), P19 (R268.1 U25.14)
CLK32K_OUT1/UART8_RX_M0/SPI1_CS1_M0/GPIO2_C6_d: P05 (M5.58), P17 (U23.42)
EDP_HPDIN_M0/SPDIF_TX_M2/SATA2_ACT_LED/PCIE30X2_PERSTn_M2/I2S3_LRCK_M1/GPIO4_C4_d: P05 (M5.29), P23 (R345.1)
EDP_ON: P12 (Q17.3 R378.2 R379.1), P23 (R355.1 U38.19)
EDP_PWM4: P05 (M5.22), P12 (R89.1 U14.2), P14 (R108.1)
EDP_TX_AUXN: P05 (M5.197), P12 (C99.2)
EDP_TX_AUXP: P05 (M5.198), P12 (C100.2)
EDP_TX_D0N: P05 (M5.203), P12 (C105.2)
EDP_TX_D0P: P05 (M5.204), P12 (C106.2)
EDP_TX_D1N: P05 (M5.201), P12 (C103.2)
EDP_TX_D1P: P05 (M5.202), P12 (C104.2)
EDP_TX_D2N: P05 (M5.199), P12 (C101.2)
EDP_TX_D2P: P05 (M5.200), P12 (C102.2)
EDP_TX_D3N: P05 (M5.195), P12 (C97.2)
EDP_TX_D3P: P05 (M5.196), P12 (C98.2)
EXT_EN: P04 (R16.1), P05 (M5.7)
FE2.1_DM7: P08 (U8.37), P22 (R335.2)
FE2.1_DP7: P08 (U8.38), P22 (R336.2)
GMAC0_INT/PMEB_GPIO3_B0: P05 (M5.119), P18 (R215.2)
GMAC0_MCLKINOUT: P05 (M5.54), P18 (C171.2 R193.1 R194.1)
GMAC0_MDC: P05 (M5.55), P18 (U24.13)
GMAC0_MDIO: P05 (M5.56), P18 (R220.1 U24.14)
GMAC0_RSTn_GPIO3_A5: P05 (M5.122), P18 (R219.1)
GMAC0_RXCLK: P05 (M5.41), P18 (C186.2 R227.2)
GMAC0_RXD0: P05 (M5.50), P18 (R223.2)
GMAC0_RXD1: P05 (M5.51), P18 (R224.2)
GMAC0_RXD2: P05 (M5.39), P18 (R225.2)
GMAC0_RXD3: P05 (M5.40), P18 (R226.2)
GMAC0_RXDV_CRS: P05 (M5.52), P18 (R228.2)
GMAC0_TXCLK: P05 (M5.44), P18 (C493.2 R205.1)
GMAC0_TXD0: P05 (M5.47), P18 (R197.1)
GMAC0_TXD1: P05 (M5.48), P18 (R198.1)
GMAC0_TXD2: P05 (M5.42), P18 (R201.1)
GMAC0_TXD3: P05 (M5.43), P18 (R202.1)
GMAC0_TXEN: P05 (M5.49), P18 (R204.1)
GMAC1_INT/PMEB_GPIO3_C1: P05 (M5.110), P19 (R262.2)
GMAC1_RSTn_GPIO3_A6: P05 (M5.121), P19 (R267.1)
GMAC1_RXDV_CRS_M1: P05 (M5.78), P19 (R276.2)
GMAC1_TXEN_M1: P05 (M5.81), P19 (R252.1)
HDMI_TX_CLKN: P05 (M5.153), P11 (L26.2)
HDMI_TX_CLKP: P05 (M5.154), P11 (L26.1)
HDMI_TX_D0N: P05 (M5.155), P11 (L25.2)
HDMI_TX_D0P: P05 (M5.156), P11 (L25.1)
HDMI_TX_D1N: P05 (M5.157), P11 (L24.2)
HDMI_TX_D1P: P05 (M5.158), P11 (L24.1)
HDMI_TX_D2N: P05 (M5.159), P11 (L23.2)
HDMI_TX_D2P: P05 (M5.160), P11 (L23.1)
HDMI_TX_HPDIN: P05 (M5.148), P11 (R85.1)
HDMITX_CEC_M0: P05 (M5.151), P11 (Q5.2 R87.2)
HDMITX_CEC_M1/PWM0_M1/UART0_CTSn/GPIO0_C7_d: P04 (R8.1), P05 (M5.26)
HDMITX_SCL/I2C5_SCL_M1/GPIO4_C7_u: P05 (M5.150), P11 (Q3.2 R81.2)
HDMITX_SDA/I2C5_SDA_M1/GPIO4_D0_u: P05 (M5.149), P11 (Q4.2 R83.2)
HOST_WAKE_BT_H_GPIO3_A2: P05 (M5.125), P17 (R162.1)
HP_DET_H_GPIO0_C5: P05 (M5.24), P10 (C82.2 R72.2 R74.1)
HP_SNS: P05 (M5.10), P10 (R77.1)
HPL_OUT: P05 (M5.9), P10 (C86.2 R73.1)
HPR_OUT: P05 (M5.11), P10 (C89.2 R76.1)
I2C1_SCL: P05 (M5.32), P21 (R313.1 R316.2), P23 (R344.1)
I2C1_SDA: P05 (M5.33), P21 (R312.1 R317.2), P23 (R343.1)
I2C2_SCL_M0: P05 (M5.34), P21 (R318.1 R320.1)
I2C2_SDA_M0: P05 (M5.35), P21 (R319.1 R321.1)
I2C3_SCL_M1: P05 (M5.114), P14 (R109.1 R113.1)
I2C3_SDA_M1: P05 (M5.113), P14 (R110.1 R114.1)
I2C4_SCL_M0/EBC_GDOE/ETH1_REFCLKO_25M_M1/SPI3_CLK_M0/I2S2_SDO_M1/GPIO4_B3_d: P05 (M5.76), P16 (R144.1 R147.1)
I2C4_SDA_M0/EBC_VCOM/GMAC1_RXER_M1/SPI3_MOSI_M0/I2S2_SDI_M1/GPIO4_B2_d: P05 (M5.77), P16 (R145.1 R146.1)
I2S2_MCLK_M0/ETH0_REFCLKO_25M/UART7_RTSn_M0/SPI2_CLK_M0/GPIO2_C1_d: P05 (M5.53), P16 (R142.1)
I2S2_SDI_M0/GMAC0_RXER/UART8_TX_M0/SPI2_CS1_M0/GPIO2_C5_d: P05 (M5.57), P17 (U23.43)
LCDC_D10/VOP_BT1120_D2/GMAC1_TXD3_M0/I2S3_SCLK_M0/SDMMC2_D2_M1/GPIO3_A3_d: P05 (M5.124), P16 (R377.1)
LCDC_D16/VOP_BT1120_D7/GMAC1_RXD0_M0/UART4_RX_M1/PWM8_M0/GPIO3_B1_d: P05 (M5.118), P20 (R371.1 R385.1)
LCDC_D17/VOP_BT1120_D8/GMAC1_RXD1_M0/UART4_TX_M1/PWM9_M0/GPIO3_B2_d: P05 (M5.117), P20 (R284.1 U26.10)
LCDC_D18/VOP_BT1120_D9/GMAC1_RXDV_CRS_M0/I2C5_SCL_M0/PDM_SDI0_M2/GPIO3_B3_d: P05 (M5.116), P14 (R111.1)
LCDC_D19/VOP_BT1120_D10/GMAC1_RXER_M0/I2C5_SDA_M0/PDM_SDI1_M2/GPIO3_B4_d: P05 (M5.115), P14 (R112.1)
LCDC_D22/PWM12_M0/GMAC1_TXEN_M0/UART3_TX_M1/PDM_SDI2_M2/GPIO3_B7_d: P05 (M5.112), P20 (R282.1 U26.11)
LCDC_D23/PWM13_M0/GMAC1_MCLKINOUT_M0/UART3_RX_M1/PDM_SDI3_M2/GPIO3_C0_d: P05 (M5.111), P20 (R370.1 R384.1)
LCDC_DEN/VOP_BT1120_D15/SPI1_CLK_M1/UART5_RX_M1/I2S1_SCLK_RX_M2/GPIO3_C3_d: P05 (M5.108), P20 (D82.A R287.2 R373.1)
LCDC_VSYNC/VOP_BT1120_D14/SPI1_MISO_M1/UART5_TX_M1/I2S1_SDO3_M2/GPIO3_C2_d: P05 (M5.109), P20 (D84.C R286.1 R288.1 U27.11)
LCM_VIO_EN: P12 (Q7.1), P15 (Q10.1), P23 (R359.1 U38.15)
LVDS_ON: P15 (Q8.3 R126.2 R128.1), P23 (R358.1 U38.16)
LVDS_PWM5: P05 (M5.23), P13 (R102.1), P15 (R130.1 U18.2)
MIC1_INN: P05 (M5.13), P10 (D41.1 J15.4 R68.1 R70.1)
MIC1_INP: P05 (M5.12), P10 (C84.2 D42.1 J16.2 R78.2)
MIPI_CSI_RX_CLK0N/PCIE30_REFCLKN_IN: P05 (M5.170), P16 (R141.1)
MIPI_CSI_RX_CLK0P/PCIE30_REFCLKP_IN: P05 (M5.169), P16 (R140.1)
MIPI_CSI_RX_D0N/PCIE30_TX0N: P05 (M5.162), P16 (R133.1)
MIPI_CSI_RX_D0P/PCIE30_TX0P: P05 (M5.161), P16 (R132.1)
MIPI_CSI_RX_D1N/PCIE30_TX1N: P05 (M5.164), P16 (R135.1)
MIPI_CSI_RX_D1P/PCIE30_TX1P: P05 (M5.163), P16 (R134.1)
MIPI_CSI_RX_D2N/PCIE30_RX0N: P05 (M5.166), P16 (R137.1)
MIPI_CSI_RX_D2P/PCIE30_RX0P: P05 (M5.165), P16 (R136.1)
MIPI_CSI_RX_D3N/PCIE30_RX1N: P05 (M5.168), P16 (R139.1)
MIPI_CSI_RX_D3P/PCIE30_RX1P: P05 (M5.167), P16 (R138.1)
MIPI_DSI_TX0_CLKN: P05 (M5.142), P13 (R98.1), P15 (U17.19)
MIPI_DSI_TX0_CLKP: P05 (M5.143), P13 (R97.1), P15 (U17.18)
MIPI_DSI_TX0_D0N: P05 (M5.146), P13 (R94.1), P15 (U17.15)
MIPI_DSI_TX0_D0P: P05 (M5.147), P13 (R93.1), P15 (U17.14)
MIPI_DSI_TX0_D1N: P05 (M5.144), P13 (R96.1), P15 (U17.17)
MIPI_DSI_TX0_D1P: P05 (M5.145), P13 (R95.1), P15 (U17.16)
MIPI_DSI_TX0_D2N: P05 (M5.140), P13 (R100.1), P15 (U17.21)
MIPI_DSI_TX0_D2P: P05 (M5.141), P13 (R99.1), P15 (U17.20)
MIPI_DSI_TX0_D3N: P05 (M5.138), P13 (R101.1), P15 (U17.23)
MIPI_DSI_TX0_D3P: P05 (M5.139), P13 (R92.1), P15 (U17.22)
MIPI_DSI_TX1_CLKN: P05 (M5.132), P14 (D58.2 D58.9 J23.27)
MIPI_DSI_TX1_CLKP: P05 (M5.133), P14 (D58.1 D58.10 J23.26)
MIPI_DSI_TX1_D0N: P05 (M5.136), P14 (D61.2 J23.33)
MIPI_DSI_TX1_D0P: P05 (M5.137), P14 (D59.2 J23.32)
MIPI_DSI_TX1_D1N: P05 (M5.134), P14 (D58.5 D58.6 J23.30)
MIPI_DSI_TX1_D1P: P05 (M5.135), P14 (D58.4 D58.7 J23.29)
MIPI_DSI_TX1_D2N: P05 (M5.130), P14 (D57.5 D57.6 J23.24)
MIPI_DSI_TX1_D2P: P05 (M5.131), P14 (D57.4 D57.7 J23.23)
MIPI_DSI_TX1_D3N: P05 (M5.128), P14 (D57.2 D57.9 J23.21)
MIPI_DSI_TX1_D3P: P05 (M5.129), P14 (D57.1 D57.10 J23.20)
PCA9539_IO0_0: P07 (R36.1 U5.4), P23 (R353.1 U38.4)
PCA9539_IO0_1: P08 (R39.1), P23 (R352.1 U38.5)
PCA9539_IO0_2: P08 (R40.1 U6.4), P23 (R351.1 U38.6)
PCA9539_IO0_3: P08 (R42.1 U7.4), P23 (R350.1 U38.7)
PCA9539_IO0_4: P08 (R47.1 U9.4), P23 (R349.1 U38.8)
PCA9539_IO0_5: P08 (R52.1 U10.4), P23 (R348.1 U38.9)
PCA9539_IO0_6: P08 (R56.1 U11.4), P23 (R347.1 U38.10)
PCA9539_IO0_7: P17 (Q13.1), P23 (R346.1 U38.11)
PCA9539_IO1_0: P10 (Q1.1), P23 (R361.1 U38.13)
PCA9539_IO1_1: P10 (Q2.1), P23 (R360.1 U38.14)
PCA9539_IO1_4: P08 (R382.1 U40.4), P23 (R357.1 U38.17)
PCA9539_IO1_5: P22 (R342.1), P23 (R356.1 U38.18)
PCIE20_REFCLKN: P05 (M5.178), P22 (R331.2)
PCIE20_REFCLKP: P05 (M5.177), P22 (R328.2)
PCIE20_RXN: P05 (M5.176), P22 (R333.2)
PCIE20_RXP: P05 (M5.175), P22 (R332.2)
PCIE20_TXN: P05 (M5.174), P22 (C251.2)
PCIE20_TXP: P05 (M5.173), P22 (C249.2)
PWM1_M0/GPUAVS/UART0_RX/GPIO0_C0_d: P05 (M5.19), P20 (R372.1 R383.1)
PWM2_M0/NPUAVS/UART0_TX/MCU_JTAG_TDI/GPIO0_C1_d: P05 (M5.20), P20 (R278.1 U27.10)
PWM3_IR/EDP_HPDIN_M1/PCIE30X1_WAKEn_M0/MCU_JTAG_TMS/GPIO0_C2_d: P05 (M5.21), P12 (R88.1)
PWM7_IR: P05 (M5.25), P09 (D102.1 J14.7)
PWM12_M1/SPI3_MISO_M1/SATA1_ACT_LED/UART9_TX_M1/I2S3_SDO_M1/GPIO4_C5_d: P05 (M5.30), P09 (D100.1 J14.5)
PWM13_M1/SPI3_CS0_M1/SATA0_ACT_LED/UART9_RX_M1/I2S3_SDI_M1/GPIO4_C6_d: P05 (M5.31), P09 (D101.1 J14.6)
PWM14_M0/VOP_PWM_M1/GMAC1_MDC_M0/UART7_TX_M1/PDM_CLK1_M2/GPIO3_C4_d: P05 (M5.107), P20 (D88.C R291.1 R295.1)
PWM14_M1/SPI3_CLK_M1/CAN1_RX_M1/PCIE30X2_CLKREQn_M2/I2S3_MCLK_M1/GPIO4_C2_d: P05 (M5.27), P09 (D98.1 J14.3)
PWM15_IR_M0/SPDIF_TX_M1/GMAC1_MDIO_M0/UART7_RX_M1/I2S1_LRCK_RX_M2/GPIO3_C5_d: P05 (M5.106), P20 (D86.A R294.2)
PWM15_IR_M1/SPI3_MOSI_M1/CAN1_TX_M1/PCIE30X2_WAKEn_M2/I2S3_SCLK_M1/GPIO4_C3_d: P05 (M5.28), P09 (D99.1 J14.4)
RK809_PWRON: P05 (M5.8), P09 (D34.1 J13.2)
RK809_VDC: P04 (C14.2 R7.2 R10.1), P05 (M5.6)
RTC_32KOUT: P17 (R177.1), P21 (U34.7)
SARADC_VIN0_KEY/RECOVERY: P05 (M5.15), P09 (D33.1 R62.1)
SARADC_VIN2_HP_HOOK: P05 (M5.16), P09 (D35.1 J13.3), P10 (C81.2 R70.2 R71.1)
SARADC_VIN4: P05 (M5.17), P09 (J13.4)
SARADC_VIN5: P05 (M5.18), P09 (J13.5)
SDMMC0_CLK: P05 (M5.63), P06 (R21.1)
SDMMC0_CMD: P05 (M5.64), P06 (R20.1)
SDMMC0_D0: P05 (M5.68), P06 (R22.1)
SDMMC0_D1: P05 (M5.67), P06 (R23.1)
SDMMC0_D2: P05 (M5.66), P06 (R18.1)
SDMMC0_D3: P05 (M5.65), P06 (R19.1)
SDMMC0_DET/SATA_CP_DET/PCIE30X1_CLKREQn_M0/GPIO0_A4_u: P05 (M5.62), P06 (R24.1)
SDMMC0_PWREN/SATA_MP_SWITCH/PCIE20_CLKREQn_M0/GPIO0_A5_d: P05 (M5.61), P07 (R34.1 U4.4)
SDMMC1_DET/I2C4_SCL_M1/UART8_CTSn_M0/CAN2_TX_M1/GPIO2_B2_u: P05 (M5.46), P17 (R173.1 U23.41)
SDMMC1_PWREN/I2C4_SDA_M1/UART8_RTSn_M0/CAN2_RX_M1/GPIO2_B1_d: P05 (M5.45), P17 (U23.44)
UART2_RX_M0: P05 (M5.60), P06 (R26.1)
UART2_TX_M0: P05 (M5.59), P06 (R27.1)
USB2_HOST2_DM: P05 (M5.99), P08 (R51.2)
USB2_HOST2_DP: P05 (M5.100), P08 (R50.2)
USB2_HOST3_DM: P05 (M5.101), P08 (L7.2)
USB2_HOST3_DP: P05 (M5.102), P08 (L7.1)
USB3_HOST1_DM: P05 (M5.182), P07 (L6.1)
USB3_HOST1_DP: P05 (M5.183), P07 (L6.2)
USB3_HOST1_SSRXN: P05 (M5.185), P07 (C50.2 R32.1)
USB3_HOST1_SSRXP: P05 (M5.184), P07 (C51.2 R33.1)
USB3_HOST1_SSTXN: P05 (M5.181), P07 (C40.1 C47.2)
USB3_HOST1_SSTXP: P05 (M5.180), P07 (C42.1 C46.2)
USB3_OTG0_DM: P05 (M5.188), P07 (L5.1)
USB3_OTG0_DP: P05 (M5.189), P07 (L5.2)
USB3_OTG0_SSRXN: P05 (M5.191), P07 (R30.1)
USB3_OTG0_SSRXP: P05 (M5.190), P07 (R31.1)
USB3_OTG0_SSTXN: P05 (M5.187), P07 (C36.1)
USB3_OTG0_SSTXP: P05 (M5.186), P07 (C37.1)
USB3_OTG0_VBUSDET: P05 (M5.192), P07 (R28.1 R29.1)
